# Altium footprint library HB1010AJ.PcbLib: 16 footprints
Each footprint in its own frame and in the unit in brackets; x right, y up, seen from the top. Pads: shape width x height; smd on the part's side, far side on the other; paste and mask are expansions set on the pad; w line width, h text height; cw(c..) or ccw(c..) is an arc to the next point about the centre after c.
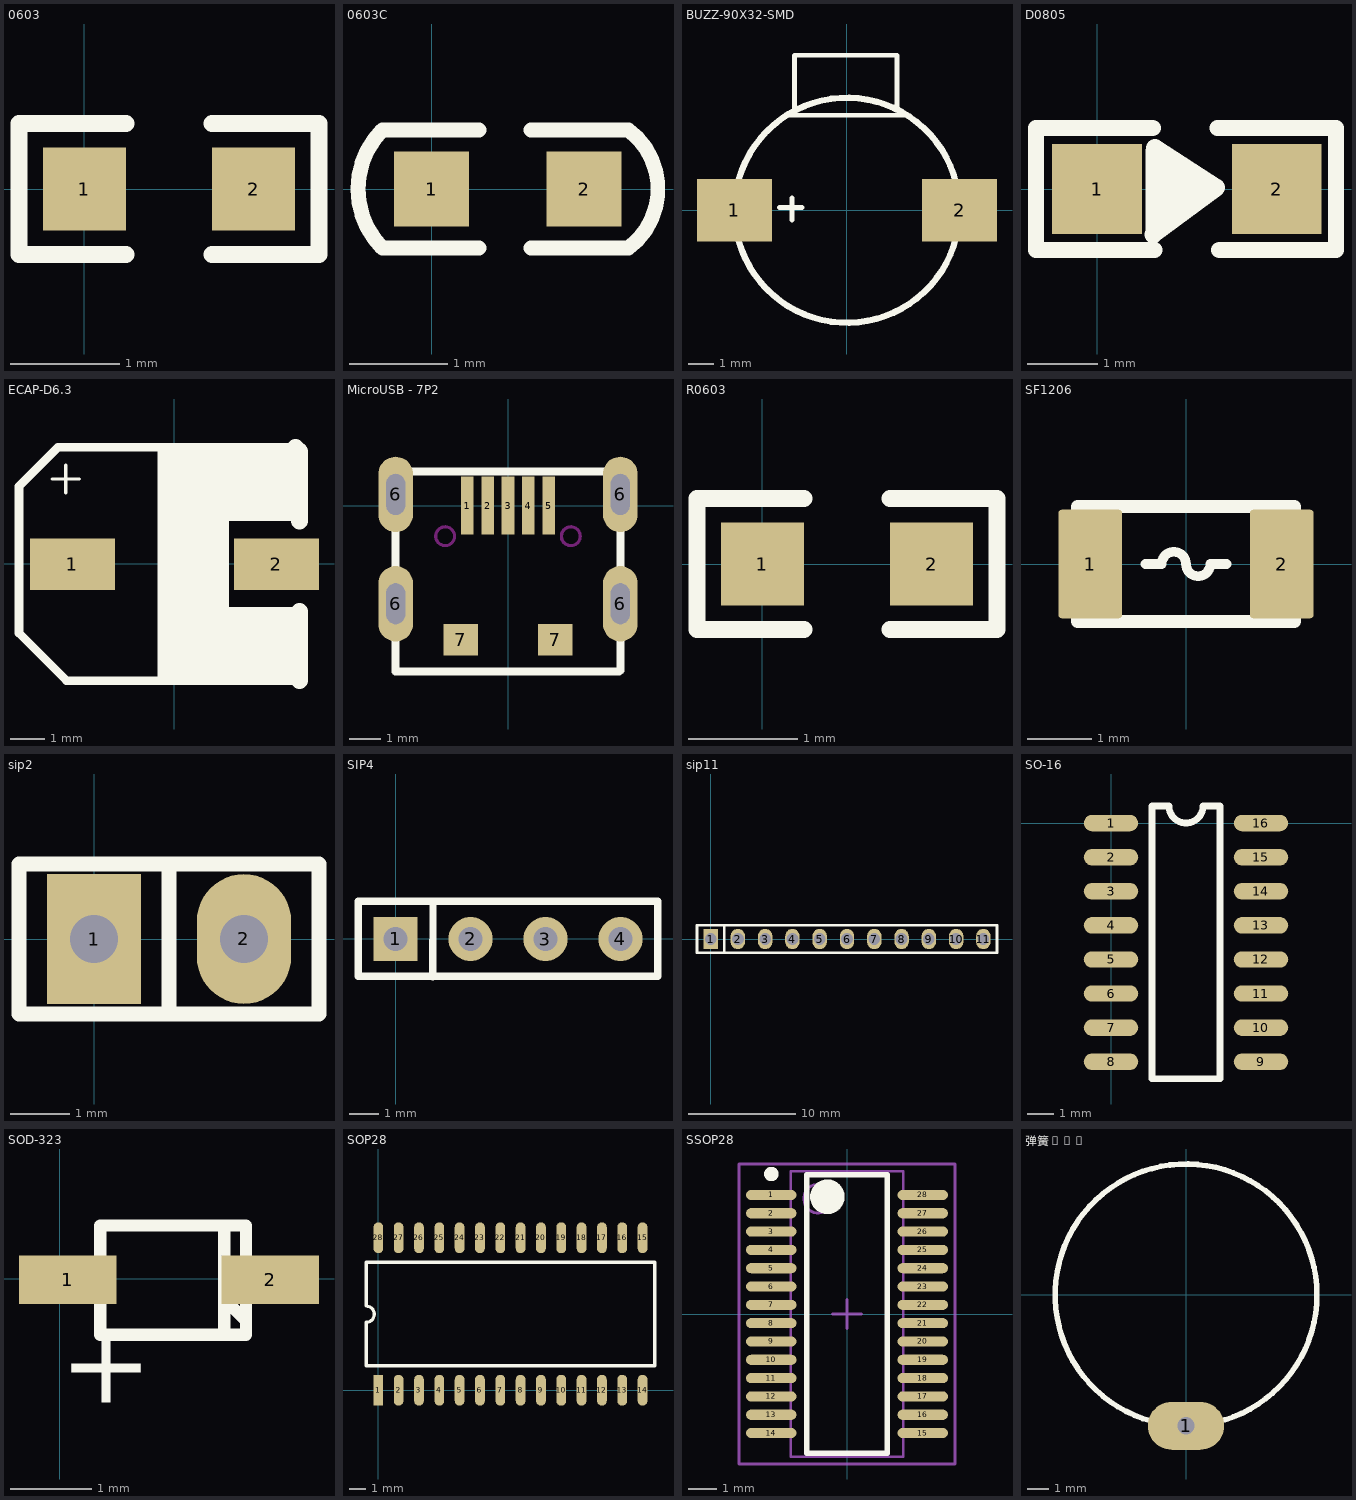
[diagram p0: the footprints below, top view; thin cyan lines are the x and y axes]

## 0603 [mil]
pads (2):
  rect 30x30 smd: 1(0,0) 2(61.02,0)
Top Overlay:
  lines w6: 15,-23.62 -23.62,-23.62 -23.62,23.62 15,23.62 ; 46,-23.62 84.65,-23.62 84.65,23.62 46,23.62

## 0603C [mil]
pads (2):
  rect 30x30 smd: 1(0,0) 2(61.02,0)
Top Overlay:
  lines w5.98: -19.69,-23.62 cw(c3.94,0) -19.69,23.62 ; 78.74,-23.62 ccw(c61.02,0) 78.74,23.62
  lines w6: -19.68,-23.62 18.94,-23.62 ; -19.68,23.62 18.94,23.62 ; 39.74,-23.62 78.74,-23.62 ; 39.74,23.62 78.74,23.62

## BUZZ-90X32-SMD [mm]
pads (2):
  rect 3x2.5 smd: 1(-4.5,0) 2(4.5,0)
Top Overlay:
  circle w0.254: c0,0 r4.5
  lines w0.2: -2.7,0.1 -1.8,0.1 ; -2.3,3.8 2.3,3.8 2,4.1 2,6.2 -2.1,6.2 -2.1,3.9 ; -2.2,-0.4 -2.2,0.5

## D0805 [mil]
height 62.99
pads (2):
  rect 50x50 smd: 1(0,0) 2(100,0)
Top Overlay:
  rectangle: 29.57,-21.62 43.57,21.38
  rectangle: 40.82,-10.46 58.3,10.32
  lines w5: 29.57,-24.41 29.57,21.38
  lines w9: 31,34 -34,34 -34,-34 32,-34 ; 67,34 133,34 133,-34 68,-34
  lines w10: 31.27,-25.28 66.27,0.72 32.27,22.72

## ECAP-D6.3 [mm]
pads (2):
  rect 2.5x1.5 smd: 1(-3,-0.007) 2(3,-0.007)
Top Overlay:
  rectangle: -0.5,-3.429 1.6,3.429
  rectangle: 0.763,1.27 3.684,3.429
  rectangle: 0.89,-3.429 3.684,-1.27
  lines w0.1: -3.6,2.5 -2.8,2.5 ; -3.2,2.1 -3.2,2.9
  lines w0.254: 3.556,3.429 -3.429,3.429 -4.572,2.286 -4.572,1.778 -4.572,-2.032 -3.175,-3.429 3.683,-3.429
  lines w0.5: 0.889,-3.175 0.889,3.175 ; 3.556,3.429 3.683,3.302 3.683,1.27 ; 3.683,-3.429 3.683,-1.397 3.683,-3.429

## MicroUSB - 7P2 [mm] "MicroUSB"
height 1.1
pads (11):
  rect 0.4x1.85 smd: 1(-1.3,0) 2(-0.65,0) 3(0,0) 4(0.65,0) 5(1.3,0)
  oval 1.1x2.4 hole 0.6 slot 1.3 at 90 deg: 6(-3.575,-3.125) 6(-3.575,0.355) 6(3.575,-3.125) 6(3.575,0.355)
  rect 1.1x1 smd: 7(-1.5,-4.275) 7(1.5,-4.275)
Top Overlay:
  lines w0.254: -3.581,-5.275 3.531,-5.275 ; -3.581,-5.232 -3.581,1.092 3.581,1.092 3.581,-5.258
Keep-Out Layer:
  circle w0.1: c2,-0.975 r0.3
  circle w0.1: c-2,-0.975 r0.3

## R0603 [mil]
pads (2):
  rect 30x30 smd: 1(0,0) 2(61.02,0)
Top Overlay:
  lines w6: 15,-23.62 -23.62,-23.62 -23.62,23.62 15,23.62 ; 46,-23.62 84.65,-23.62 84.65,23.62 46,23.62

## SF1206 [mm]
pads (2):
  rrect10% 1x1.7 smd: 1(-1.5,0) 2(1.5,0)
Top Overlay:
  lines w0.152: -0.635,0 -0.381,0 cw(c-0.191,0) 0,0 ccw(c0.191,0) 0.381,0 0.635,0
  lines w0.203: -1.7,-0.9 1.7,-0.9 1.7,0.9 -1.7,0.9 -1.7,-0.9

## sip2 [mm]
pads (2):
  rect 1.6x2.2 hole 0.813: 1(0,0)
  oval 1.6x2.2 hole 0.813: 2(2.54,0)
Top Overlay:
  lines w0.254: 1.27,-1.27 1.27,1.27 ; -1.27,-1.27 -1.27,1.27 3.81,1.27 3.81,-1.27 -1.27,-1.27

## SIP4 [mm]
pads (4):
  rect 1.5x1.5 hole 0.813: 1(0,0)
  round 1.5 hole 0.813: 2(2.54,0) 3(5.08,0) 4(7.62,0)
Top Overlay:
  lines w0.254: 1.27,-1.27 1.27,1.27 ; -1.27,-1.27 -1.27,1.27 8.89,1.27 8.89,-1.27 -1.27,-1.27

## sip11 [mil]
pads (11):
  rect 53x75 hole 43: 1(0,0)
  oval 53x75 hole 43: 2(100,0) 3(200,0) 4(300,0) 5(400,0) 6(500,0) 7(600,0) 8(700,0) 9(800,0) 10(900,0) 11(1000,0)
Top Overlay:
  lines w10: 50,-50 50,50 ; -50,-50 -50,50 1050,50 1050,-50 -50,-50

## SO-16 [mil]
height 175.2
pads (16):
  oval 80x24 smd: 1(0,0) 2(0,-50) 3(0,-100) 4(0,-150) 5(0,-200) 6(0,-250) 7(0,-300) 8(0,-350) 9(220,-350) 10(220,-300) 11(220,-250) 12(220,-200) 13(220,-150) 14(220,-100) 15(220,-50) 16(220,0)
Top Overlay:
  lines w10: 60,-375 60,25 85,25 ccw(c110,25) 135,25 160,25 160,-375 60,-375

## SOD-323 [mm]
pads (2):
  rect 1.2x0.6 smd: 1(0.1,-0.007) 2(2.6,-0.007)
Top Overlay:
  lines w0.152: 2.032,-0.69 2.032,0.66 ; 2.032,-0.007 2.032,-0.247 2.3,-0.515 ; 2.032,0.501 2.032,0.261 2.3,-0.007 ; 0.5,-0.69 2.3,-0.69 2.3,0.66 0.5,0.66 0.5,-0.69
  text "+" at 0,-1.524 h1

## SOP28 [mil]
height 43.31
pads (28):
  rect 24x76 smd: 1(0,0)
  oval 24x76 smd: 2(50,0) 3(100,0) 4(150,0) 5(200,0) 6(250,0) 7(300,0) 8(350,0) 9(400,0) 10(450,0) 11(500,0) 12(550,0) 13(600,0) 14(650,0) 15(650,375) 16(600,375) 17(550,375) 18(500,375) 19(450,375) 20(400,375) 21(350,375) 22(300,375) 23(250,375) 24(200,375) 25(150,375) 26(100,375) 27(50,375) 28(0,375)
Top Overlay:
  lines w8: -30,60 -30,167 ccw(c-30,187) -30,207 -30,315 680,315 680,60 -30,60

## SSOP28 [mm]
height 1.75
pads (28):
  oval 1.75x0.35 smd: 1(-2.625,4.127) 2(-2.625,3.492) 3(-2.625,2.857) 4(-2.625,2.222) 5(-2.625,1.587) 6(-2.625,0.953) 7(-2.625,0.318) 8(-2.625,-0.318) 9(-2.625,-0.953) 10(-2.625,-1.587) 11(-2.625,-2.222) 12(-2.625,-2.857) 13(-2.625,-3.492) 14(-2.625,-4.127) 15(2.625,-4.127) 16(2.625,-3.492) 17(2.625,-2.857) 18(2.625,-2.222) 19(2.625,-1.587) 20(2.625,-0.953) 21(2.625,-0.318) 22(2.625,0.318) 23(2.625,0.953) 24(2.625,1.587) 25(2.625,2.222) 26(2.625,2.857) 27(2.625,3.492) 28(2.625,4.127)
Top Overlay:
  circle w0.25: c-2.625,4.852 r0.125
  circle w0.6: c-0.681,4.064 r0.3
  lines w0.2: -1.397,-4.826 -1.397,4.826 1.397,4.826 1.397,-4.826 -1.397,-4.826
Mechanical 13:
  circle w0.1: c-1,4 r0.5
  lines w0.1: -1.95,-4.95 -1.95,4.95 1.95,4.95 1.95,-4.95 -1.95,-4.95
Mechanical 15:
  lines w0.1: -0.5,0 0.5,0 ; 0,-0.5 0,0.5 ; -3.75,-5.2 -3.75,5.2 3.75,5.2 3.75,-5.2 -3.75,-5.2
3D body: height 1.75, standoff 0.23, extent -1.95,-4.95 1.95,4.95

## 弹簧6MM [mm]
pads (1):
  oval 3.5x2.2 hole 0.8: 1(0,-6)
Top Overlay:
  circle w0.254: c0,0 r6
